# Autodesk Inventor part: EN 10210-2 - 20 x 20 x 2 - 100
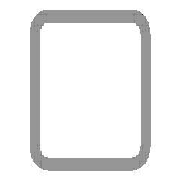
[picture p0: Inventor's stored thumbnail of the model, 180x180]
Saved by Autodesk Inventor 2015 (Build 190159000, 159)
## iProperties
Created: 2015-05
Part Number: EN 10210-2 - 20 x 20 x 2 - 100
Material: Steel, Mild
Description: Tube
Document SubType Name: Modeling
Standard: DIN
Designer: TREINA6
Standard Revision: 1997
Standards Organization: DIN
Language: en-US
Size Designation: 20 x 20 x 2
Categories: <MemberInstance><Categories><Category DisplayName="Structural Shapes" InternalName="089c4875-fa83-4c05-b084-43b9cc11f5ed" Mnemonic="GRDR"><CategoryParameter Dis
Stock Number: 20 x 20 x 2
Density: 7.85 g/cm^3
Appearance: Semi-Polished
_CCFamilyMember: 1
_CCFamilyDisplayName: DIN EN 10210-2 (Square) - Tube
_FrameMemberDoc: Frame Member File
_Version: 15.0.0
_GetPNFromCC: 1
IsCustomPart: 1
Author: TREINA6
G_L: 100,000 mm
G_W: 20,000 mm
G_H: 20,000 mm
+1C2C2078-6D63-4675-889F-DB36AB8CDDC0+CUTDETAIL1: Miter 45,00 deg
+BB4E3DC9-09CA-4539-8D1D-C4E5F17BFB93+CUTDETAIL2: Miter 45,00 deg
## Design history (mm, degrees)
node "Start plane"
node "End plane"
sketch "Sketch"
  geometry: L1 (-10, -7)-(-10, 7); L2 (-7, 10)-(7, 10); L3 (10, 7)-(10, -7); L4 (7, -10)-(-7, -10); L5 (-7, 8)-(7, 8); L6 (8, 7)-(8, -7); L7 (7, -8)-(-7, -8); L8 (-8, -7)-(-8, 7); L9 (0, 14.87)-(0, -14.87) reference; L10 (-14.87, 0)-(14.87, 0) reference; A1 r 3 centre (-7, -7) between (-10, -7) and (-7, -10); A2 r 3 centre (-7, 7) between (-7, 10) and (-10, 7); A3 r 3 centre (7, 7) between (10, 7) and (7, 10); A4 r 3 centre (7, -7) between (7, -10) and (10, -7); A5 r 1 centre (-7, 7) between (-7, 8) and (-8, 7); A6 r 1 centre (7, 7) between (8, 7) and (7, 8); A7 r 1 centre (7, -7) between (7, -8) and (8, -7); A8 r 1 centre (-7, -7) between (-8, -7) and (-7, -8)
  constraints: 16 end point, 16 point on circle, 8 centre point, 8 tangent, 4 parallel, 3 equal radius, 2 perpendicular, 7 other
  dimensions: "d7" = 3 radius of A1 (= G_IR); "d10" = 20 distance between parallel lines of L2 L4 (= G_H); "d11" = 20 distance between parallel lines of L1 L3 (= G_W); "d12" = 2 distance between parallel lines of L3 L6 (= G_T); "d15" = 10 distance between parallel lines of L2 L10 (= 0.5 x d10); "d16" = 10 distance between parallel lines of L9 L3 (= 0.5 x d11)
extrude "Body" new body sketch "Sketch" stored distance "d3" = 100 (= G_L); taper "d4" = 0 deg
node "Driven Length"
  sketch "Sketch3"
    geometry: L1 (0, 0)-(10, 0) reference
    constraints: 2 end point, 1 horizontal
  workplane "Work Plane3"
  sketch "Sketch4"
    geometry: L1 (-2, 0)-(12, 0) reference; L2 (-2, 100)-(12, 100) reference
    dimensions: "d18" = 100 distance between parallel lines of L1 L2 (derived)
workplane "Work Plane4"
split "Split1"
workplane "Work Plane5"
split "Split2"
body "Solid1"
other parameters: "G_W" = 20 [user parameter; used in 1 equation term], "G_H" = 20 [user parameter; used in 1 equation term], "G_T" = 2 [user parameter; used in 1 equation term], "G_IR" = 3 [user parameter; used in 1 equation term], "G_L" = 100 (= d18) [user parameter; used in 1 equation term], "G_OFFSET_START" = 0 [user parameter; used in 1 equation term], "G_OFFSET_END" = 0 [user parameter; used in 1 equation term], "d13" = 0 (computed from G_OFFSET_START), "d17" = 90 deg
